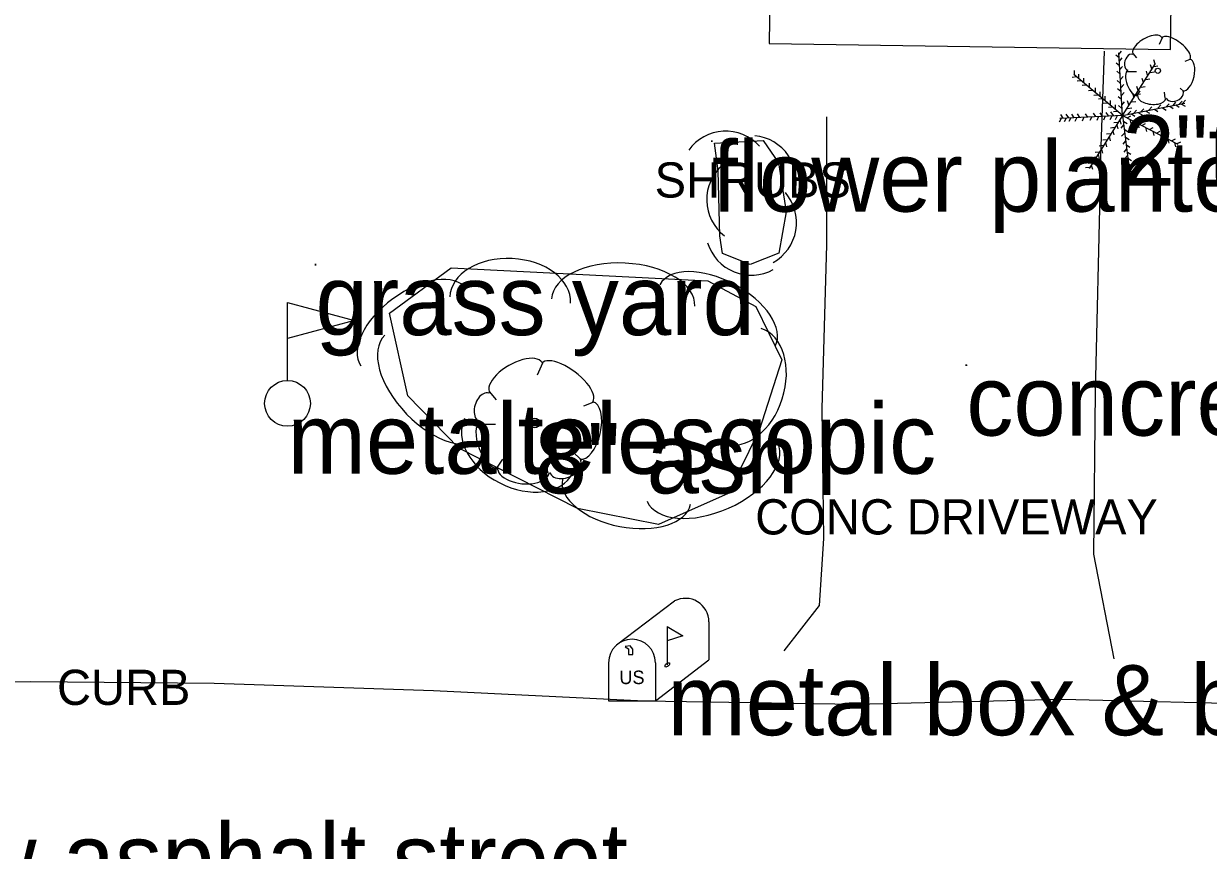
# Model space of a CAD drawing. Extents: x 1802180 to 1804859, y 572524 to 575172.
# Drawn here: x 1803606.6 to 1803690.8, y 574468.6 to 574527.4 of the extents above; entities that cross this region are included whole.
import ezdxf

# ---------------------------------------------------------------- set-up
doc = ezdxf.new("R2010")
doc.units = 0
for name, color, linetype in [('S_BUILDING', 7, 'Continuous'), ('S_CURB_ANNOT', 7, 'Continuous'), ('S_DRIVEWAY', 7, 'Continuous'), ('S_DRIVEWAY_ANNOT', 7, 'Continuous'), ('S_EDGE_PAVEMENT', 7, 'Continuous'), ('S_FLAG_POLE', 7, 'Continuous'), ('S_FLAG_POLE_ANNOT', 7, 'Continuous'), ('S_MAILBOX', 7, 'Continuous'), ('S_MAILBOX_ANNOT', 7, 'Continuous'), ('S_MSC_PT_SYM', 7, 'Continuous'), ('S_SURVEY_TEXT_ANNOT', 7, 'Continuous'), ('S_TREE', 7, 'Continuous'), ('S_TREE_ANNOT', 7, 'Continuous')]:
    doc.layers.add(name, color=color, linetype=linetype)

msp = doc.modelspace()

# ---------------------------------------------------------------- linework, layer by layer
at = {"layer": 'S_BUILDING'}
msp.add_lwpolyline([(1803688.099, 574525.527), (1803688.857, 574576.609), (1803658.849, 574577.054), (1803659.027, 574589.016), (1803635.785, 574589.361), (1803635.609, 574577.512), (1803618.113, 574577.771), (1803617.556, 574540.224), (1803635.26, 574539.961), (1803635.284, 574541.551), (1803659.796, 574541.187), (1803659.57, 574525.951), (1803688.099, 574525.527)], dxfattribs=at)
at = {"layer": 'S_DRIVEWAY'}
for points in [[(1803684.092, 574482.234), (1803682.654, 574489.677), (1803682.752, 574501.24), (1803683.109, 574516.233), (1803683.137, 574517.975), (1803683.391, 574525.411)], [(1803660.65, 574482.819), (1803663.151, 574486.034), (1803663.453, 574490.781), (1803663.35, 574500.026), (1803663.664, 574511.656), (1803663.667, 574520.743)]]:
    msp.add_lwpolyline(points, dxfattribs=at)
at = {"layer": 'S_EDGE_PAVEMENT'}
msp.add_lwpolyline([(1803725.694, 574477.874), (1803710.309, 574478.172), (1803695.813, 574478.983), (1803680.385, 574479.352), (1803665.755, 574478.996), (1803650.699, 574479.226), (1803635.729, 574479.963), (1803620.155, 574480.487), (1803607.133, 574480.611), (1803591.104, 574480.357), (1803575.243, 574480.483)], dxfattribs=at)
at = {"layer": 'S_FLAG_POLE'}
for p, q in [((1803625.36, 574502.018), (1803625.36, 574507.559)), ((1803625.36, 574507.559), (1803630.126, 574506.28)), ((1803630.126, 574506.28), (1803625.36, 574505.002))]:
    msp.add_line(p, q, dxfattribs=at)
msp.add_circle((1803625.36, 574500.39), 1.628, dxfattribs=at)
at = {"layer": 'S_MAILBOX'}
for p, q in [((1803648.729, 574483.244), (1803652.863, 574486.352)), ((1803652.344, 574484.532), (1803652.344, 574481.817)), ((1803655.295, 574484.879), (1803655.295, 574482.164)), ((1803648.175, 574481.97), (1803648.175, 574479.255)), ((1803651.499, 574479.255), (1803655.295, 574482.164)), ((1803651.499, 574481.97), (1803651.499, 574479.255)), ((1803648.175, 574479.255), (1803651.499, 574479.255))]:
    msp.add_line(p, q, dxfattribs=at)
for points in [[(1803652.344, 574484.532), (1803653.453, 574483.868), (1803652.344, 574483.521)], [(1803649.359, 574483.085), (1803649.581, 574482.946), (1803649.581, 574482.558), (1803649.886, 574482.558), (1803649.886, 574482.919), (1803649.692, 574483.168), (1803649.359, 574483.113)]]:
    msp.add_lwpolyline(points, dxfattribs=at)
for centre, end in [((1803653.633, 574484.879), 117.57184), ((1803649.837, 574481.97), 180)]:
    msp.add_arc(centre, 1.662, 0, end, dxfattribs=at)
msp.add_ellipse((1803652.344, 574481.817), major_axis=(0.145, 0.132), ratio=0.564646, dxfattribs=at)
at = {"layer": 'S_MSC_PT_SYM'}
for points in [[(1803655.507, 574519.009), (1803655.507, 574519.059), (1803655.507, 574519.009), (1803655.457, 574519.009), (1803655.507, 574519.009), (1803655.507, 574518.959), (1803655.507, 574519.009), (1803655.557, 574519.009)], [(1803627.35, 574510.241), (1803627.35, 574510.291), (1803627.35, 574510.241), (1803627.3, 574510.241), (1803627.35, 574510.241), (1803627.35, 574510.191), (1803627.35, 574510.241), (1803627.4, 574510.241)], [(1803673.584, 574503.101), (1803673.584, 574503.151), (1803673.584, 574503.101), (1803673.534, 574503.101), (1803673.584, 574503.101), (1803673.584, 574503.051), (1803673.584, 574503.101), (1803673.634, 574503.101)]]:
    msp.add_lwpolyline(points, dxfattribs=at)
at = {"layer": 'S_TREE'}
for p, q in [((1803687.5, 574526.355), (1803687.287, 574525.885)), ((1803684.433, 574524.924), (1803684.208, 574525.123)), ((1803684.688, 574520.844), (1803684.419, 574525.279)), ((1803684.43, 574525.171), (1803684.618, 574525.404)), ((1803684.459, 574524.694), (1803684.647, 574524.927)), ((1803685.405, 574525.244), (1803685.683, 574524.923)), ((1803687.004, 574524.495), (1803686.915, 574524.782)), ((1803689.467, 574524.816), (1803689.104, 574524.666)), ((1803681.262, 574523.728), (1803681.262, 574524.028)), ((1803684.465, 574524.36), (1803684.241, 574524.559)), ((1803684.494, 574523.786), (1803684.27, 574523.985)), ((1803684.491, 574524.094), (1803684.679, 574524.327)), ((1803684.688, 574520.844), (1803687.03, 574524.528)), ((1803685.042, 574523.961), (1803685.662, 574523.961)), ((1803686.462, 574523.702), (1803686.373, 574523.988)), ((1803686.649, 574523.889), (1803686.946, 574523.933)), ((1803686.759, 574524.153), (1803686.669, 574524.44)), ((1803686.894, 574524.315), (1803687.191, 574524.359)), ((1803681.404, 574523.586), (1803681.107, 574523.545)), ((1803684.688, 574520.844), (1803681.223, 574523.753)), ((1803681.752, 574523.308), (1803681.453, 574523.284)), ((1803681.578, 574523.476), (1803681.578, 574523.776)), ((1803681.933, 574523.186), (1803681.933, 574523.486)), ((1803682.346, 574522.824), (1803682.346, 574523.124)), ((1803684.52, 574523.128), (1803684.295, 574523.326)), ((1803684.53, 574523.384), (1803684.718, 574523.617)), ((1803686.165, 574523.186), (1803686.076, 574523.472)), ((1803686.326, 574523.399), (1803686.623, 574523.442)), ((1803682.113, 574522.986), (1803681.814, 574522.961)), ((1803682.572, 574522.611), (1803682.272, 574522.587)), ((1803682.933, 574522.282), (1803682.634, 574522.258)), ((1803682.759, 574522.495), (1803682.759, 574522.795)), ((1803683.081, 574522.211), (1803683.081, 574522.511)), ((1803684.559, 574522.534), (1803684.334, 574522.733)), ((1803684.594, 574522.816), (1803684.783, 574523.05)), ((1803684.607, 574522.248), (1803684.795, 574522.482)), ((1803685.494, 574522.128), (1803685.405, 574522.414)), ((1803685.655, 574522.34), (1803685.952, 574522.384)), ((1803685.683, 574522.208), (1803685.94, 574522.593)), ((1803685.791, 574522.618), (1803685.702, 574522.904)), ((1803686.004, 574522.857), (1803686.301, 574522.901)), ((1803687.714, 574522.058), (1803687.671, 574522.486)), ((1803689.04, 574522.55), (1803688.783, 574522.785)), ((1803683.268, 574522.018), (1803682.969, 574521.994)), ((1803683.61, 574521.721), (1803683.311, 574521.697)), ((1803683.449, 574521.908), (1803683.449, 574522.208)), ((1803683.978, 574521.424), (1803683.679, 574521.4)), ((1803683.817, 574521.605), (1803683.817, 574521.905)), ((1803684.172, 574521.289), (1803684.172, 574521.589)), ((1803684.597, 574521.966), (1803684.373, 574522.165)), ((1803684.61, 574521.347), (1803684.386, 574521.546)), ((1803684.633, 574521.577), (1803684.821, 574521.811)), ((1803684.688, 574520.844), (1803689.108, 574521.71)), ((1803685.133, 574521.598), (1803685.044, 574521.885)), ((1803685.32, 574521.799), (1803685.617, 574521.842)), ((1803686.561, 574521.219), (1803686.763, 574521.441)), ((1803687.193, 574521.361), (1803687.395, 574521.583)), ((1803687.787, 574521.451), (1803687.989, 574521.673)), ((1803688.036, 574521.502), (1803688.29, 574521.341)), ((1803688.271, 574521.554), (1803688.472, 574521.776)), ((1803688.462, 574521.592), (1803688.715, 574521.432)), ((1803688.716, 574521.645), (1803688.918, 574521.867)), ((1803688.868, 574521.65), (1803689.122, 574521.49)), ((1803688.942, 574521.696), (1803689.143, 574521.918)), ((1803680.32, 574520.631), (1803680.186, 574520.362)), ((1803684.688, 574520.844), (1803680.236, 574520.632)), ((1803680.469, 574520.654), (1803680.3, 574520.903)), ((1803680.668, 574520.657), (1803680.534, 574520.388)), ((1803680.856, 574520.68), (1803680.687, 574520.928)), ((1803681.01, 574520.676), (1803680.876, 574520.408)), ((1803681.256, 574520.68), (1803681.087, 574520.928)), ((1803681.43, 574520.689), (1803681.295, 574520.42)), ((1803681.656, 574520.706), (1803681.487, 574520.954)), ((1803681.939, 574520.715), (1803681.805, 574520.446)), ((1803682.224, 574520.719), (1803682.055, 574520.967)), ((1803684.688, 574520.844), (1803682.307, 574517.069)), ((1803682.501, 574520.74), (1803682.366, 574520.472)), ((1803682.778, 574520.758), (1803682.61, 574521.006)), ((1803682.984, 574520.76), (1803682.85, 574520.491)), ((1803683.256, 574520.771), (1803683.087, 574521.019)), ((1803683.455, 574520.786), (1803683.321, 574520.517)), ((1803683.695, 574520.809), (1803683.526, 574521.057)), ((1803683.913, 574520.792), (1803683.779, 574520.524)), ((1803684.03, 574520.848), (1803683.861, 574521.096)), ((1803684.339, 574521.128), (1803684.04, 574521.103)), ((1803684.301, 574520.805), (1803684.166, 574520.537)), ((1803684.688, 574520.844), (1803688.604, 574518.798)), ((1803684.688, 574520.844), (1803685.219, 574516.471)), ((1803685.017, 574520.663), (1803685.282, 574520.803)), ((1803685.036, 574521.334), (1803685.333, 574521.378)), ((1803685.064, 574520.929), (1803685.266, 574521.151)), ((1803685.197, 574520.566), (1803685.268, 574520.275)), ((1803685.307, 574520.96), (1803685.56, 574520.799)), ((1803685.464, 574520.987), (1803685.666, 574521.209)), ((1803685.494, 574520.437), (1803685.76, 574520.577)), ((1803685.823, 574521.037), (1803686.077, 574520.877)), ((1803685.993, 574521.09), (1803686.195, 574521.312)), ((1803686.339, 574521.153), (1803686.593, 574520.993)), ((1803686.946, 574521.282), (1803687.199, 574521.122)), ((1803687.526, 574521.386), (1803687.78, 574521.225)), ((1803684.12, 574519.979), (1803683.822, 574519.945)), ((1803683.991, 574519.747), (1803684.067, 574519.457)), ((1803684.359, 574520.347), (1803684.061, 574520.313)), ((1803684.268, 574520.186), (1803684.344, 574519.895)), ((1803684.481, 574520.521), (1803684.557, 574520.231)), ((1803684.749, 574520.168), (1803684.553, 574519.941)), ((1803684.765, 574520.418), (1803685.021, 574520.262)), ((1803684.804, 574519.863), (1803685.06, 574519.707)), ((1803685.778, 574520.263), (1803685.849, 574519.971)), ((1803686.049, 574520.134), (1803686.314, 574520.274)), ((1803686.314, 574519.986), (1803686.384, 574519.694)), ((1803686.604, 574519.85), (1803686.869, 574519.99)), ((1803687.088, 574519.592), (1803687.353, 574519.732)), ((1803683.591, 574519.115), (1803683.293, 574519.081)), ((1803683.475, 574518.908), (1803683.55, 574518.618)), ((1803683.843, 574519.534), (1803683.544, 574519.5)), ((1803683.733, 574519.334), (1803683.809, 574519.044)), ((1803684.814, 574519.587), (1803684.618, 574519.36)), ((1803684.898, 574519.026), (1803684.702, 574518.799)), ((1803684.888, 574519.295), (1803685.144, 574519.139)), ((1803686.836, 574519.715), (1803686.907, 574519.423)), ((1803687.372, 574519.418), (1803687.442, 574519.126)), ((1803687.623, 574519.321), (1803687.889, 574519.461)), ((1803687.888, 574519.16), (1803687.959, 574518.868)), ((1803688.172, 574519.044), (1803688.437, 574519.184)), ((1803688.378, 574518.908), (1803688.449, 574518.617)), ((1803688.565, 574518.837), (1803688.831, 574518.977)), ((1803683.03, 574518.244), (1803682.731, 574518.21)), ((1803682.946, 574518.063), (1803683.021, 574517.773)), ((1803683.326, 574518.695), (1803683.028, 574518.661)), ((1803683.191, 574518.444), (1803683.267, 574518.153)), ((1803684.969, 574518.458), (1803684.773, 574518.231)), ((1803684.952, 574518.747), (1803685.208, 574518.591)), ((1803685.023, 574518.237), (1803685.279, 574518.081)), ((1803682.539, 574517.457), (1803682.241, 574517.423)), ((1803682.462, 574517.315), (1803682.538, 574517.024)), ((1803682.791, 574517.869), (1803682.493, 574517.836)), ((1803682.688, 574517.663), (1803682.763, 574517.373)), ((1803685.033, 574518), (1803684.837, 574517.773)), ((1803685.072, 574517.619), (1803684.876, 574517.392)), ((1803685.055, 574517.805), (1803685.312, 574517.649)), ((1803685.101, 574517.398), (1803685.357, 574517.242)), ((1803682.339, 574517.153), (1803682.041, 574517.119)), ((1803685.13, 574517.174), (1803684.934, 574516.947)), ((1803685.175, 574516.755), (1803684.979, 574516.528)), ((1803685.165, 574516.934), (1803685.421, 574516.778)), ((1803685.204, 574516.592), (1803685.46, 574516.436)), ((1803643.478, 574503.243), (1803643.091, 574502.391)), ((1803639.681, 574501.228), (1803640.185, 574500.647)), ((1803647.043, 574500.453), (1803646.385, 574500.182)), ((1803639.022, 574498.903), (1803640.146, 574498.903)), ((1803640.185, 574495.726), (1803640.65, 574496.423)), ((1803643.866, 574495.455), (1803643.788, 574496.23)), ((1803646.268, 574496.346), (1803645.803, 574496.772))]:
    msp.add_line(p, q, dxfattribs=at)
for points in [[(1803656.079, 574512.287), (1803655.967, 574516.914), (1803655.69, 574518.87), (1803659.159, 574519.066), (1803660.235, 574517.469), (1803660.787, 574514.001), (1803660.268, 574511.062), (1803658.225, 574510.251), (1803656.264, 574511.042), (1803656.079, 574512.287)], [(1803636.987, 574510.015), (1803655.226, 574509.092), (1803658.625, 574507.279), (1803660.474, 574503.492), (1803658.873, 574498.468), (1803656.659, 574493.982), (1803651.722, 574491.788), (1803645.954, 574492.911), (1803637.526, 574497.206), (1803633.915, 574500.916), (1803632.597, 574506.807), (1803636.987, 574510.015)]]:
    msp.add_lwpolyline(points, dxfattribs=at)
for centre, radius in [((1803687.193, 574524.013), 0.188), ((1803642.92, 574498.998), 0.341)]:
    msp.add_circle(centre, radius, dxfattribs=at)
for centre, start, end in [((1803656.493, 574516.475), 42.42937, 144.02628), ((1803658.255, 574516.165), 343.18375, 84.78066), ((1803658.389, 574514.86), 130.59541, 232.19232), ((1803658.276, 574513.236), 299.18886, 40.78577), ((1803658.306, 574512.744), 197.24466, 298.84157)]:
    msp.add_arc(centre, 3.247, start, end, dxfattribs=at)
for centre, major_axis, ratio, start_param, end_param in [((1803686.455, 574525.78), (1.024, 0.598), 0.471018, 0, 3.141593), ((1803688.472, 574525.601), (-1, 0.75), 0.405113, 3.141593, 6.283186), ((1803685.223, 574524.613), (0.168, 0.567), 0.646762, 0, 3.141593), ((1803689.219, 574523.721), (0.253, 1.125), 0.482994, 3.141593, 6.283185), ((1803685.391, 574523.151), (-0.337, 0.88), 0.420543, 6.283185, 9.424777), ((1803686.749, 574522.168), (-1.01, 0.107), 0.529943, 0, 3.141593), ((1803688.38, 574522.33), (0.602, 0.255), 0.711534, 3.141592, 6.283185), ((1803641.177, 574507.734), (-4.294, 0.217), 0.685311, 3.141593, 6.283185), ((1803649.21, 574507.554), (-5.085, 0.258), 0.55008, 3.141593, 6.283185), ((1803634.327, 574505.792), (-3.745, -2.737), 0.540699, 3.141593, 6.283185), ((1803655.915, 574506.638), (-4.092, 2.183), 0.540699, 3.141593, 6.283185), ((1803657.705, 574501.608), (1.305, 4.096), 0.685311, 3.141593, 6.283185), ((1803635.832, 574501.585), (3.551, -3.648), 0.55008, 3.141593, 6.283185), ((1803641.584, 574502.2), (1.857, 1.085), 0.471018, 0, 3.141593), ((1803645.239, 574501.877), (-1.813, 1.36), 0.405113, 3.141593, 6.283186), ((1803639.35, 574500.085), (0.305, 1.027), 0.646762, 0, 3.141593), ((1803646.594, 574498.468), (0.458, 2.04), 0.482994, 3.141593, 6.283185), ((1803641.773, 574497.361), (3.83, -1.952), 0.685311, 3.141593, 6.283185), ((1803639.655, 574497.435), (-0.611, 1.596), 0.420543, 6.283185, 9.424777), ((1803655.553, 574495.505), (4.652, 2.068), 0.55008, 3.141593, 6.283185), ((1803645.073, 574495.947), (1.092, 0.462), 0.711534, 3.141592, 6.283185), ((1803642.116, 574495.654), (-1.832, 0.194), 0.529943, 0, 3.141593), ((1803649.44, 574494.107), (4.553, -0.886), 0.540699, 3.141593, 6.283185)]:
    msp.add_ellipse(centre, major_axis=major_axis, ratio=ratio, start_param=start_param, end_param=end_param, dxfattribs=at)

# ---------------------------------------------------------------- texts
at = {"layer": 'S_CURB_ANNOT'}
msp.add_text('CURB', height=2.5, dxfattribs=at).set_placement((1803608.988, 574478.969))
at = {"layer": 'S_DRIVEWAY_ANNOT'}
msp.add_text('CONC DRIVEWAY', height=2.5, dxfattribs=at).set_placement((1803658.586, 574491.078))
msp.add_text('CONC DRIVEWAY', height=2.5, dxfattribs=at).set_placement((1803658.586, 574491.078))
at = {"layer": 'S_FLAG_POLE_ANNOT'}
msp.add_text('metaltelescopic ', height=5, dxfattribs=at).set_placement((1803625.36, 574495.39))
at = {"layer": 'S_MAILBOX'}
msp.add_text('US', height=0.96, rotation=360, dxfattribs=at).set_placement((1803648.939, 574480.448))
at = {"layer": 'S_MAILBOX_ANNOT'}
msp.add_text('metal box & brick ', height=5, dxfattribs=at).set_placement((1803652.344, 574476.817))
at = {"layer": 'S_SURVEY_TEXT_ANNOT'}
for s, p in [('flower planter ', (1803655.507, 574514.009)), ('grass yard ', (1803627.35, 574505.241)), ('concrete drive ', (1803673.584, 574498.101)), ('northview asphalt street ', (1803578.918, 574465.565))]:
    msp.add_text(s, height=5, dxfattribs=at).set_placement(p)
at = {"layer": 'S_TREE_ANNOT'}
for s, height, p in [('2"twin holly tree ', 5, (1803684.688, 574515.844)), ('SHRUBS', 2.5, (1803651.444, 574515.009)), ('8" ash ', 5, (1803642.92, 574493.998))]:
    msp.add_text(s, height=height, dxfattribs=at).set_placement(p)

doc.saveas('drawing.dxf')
